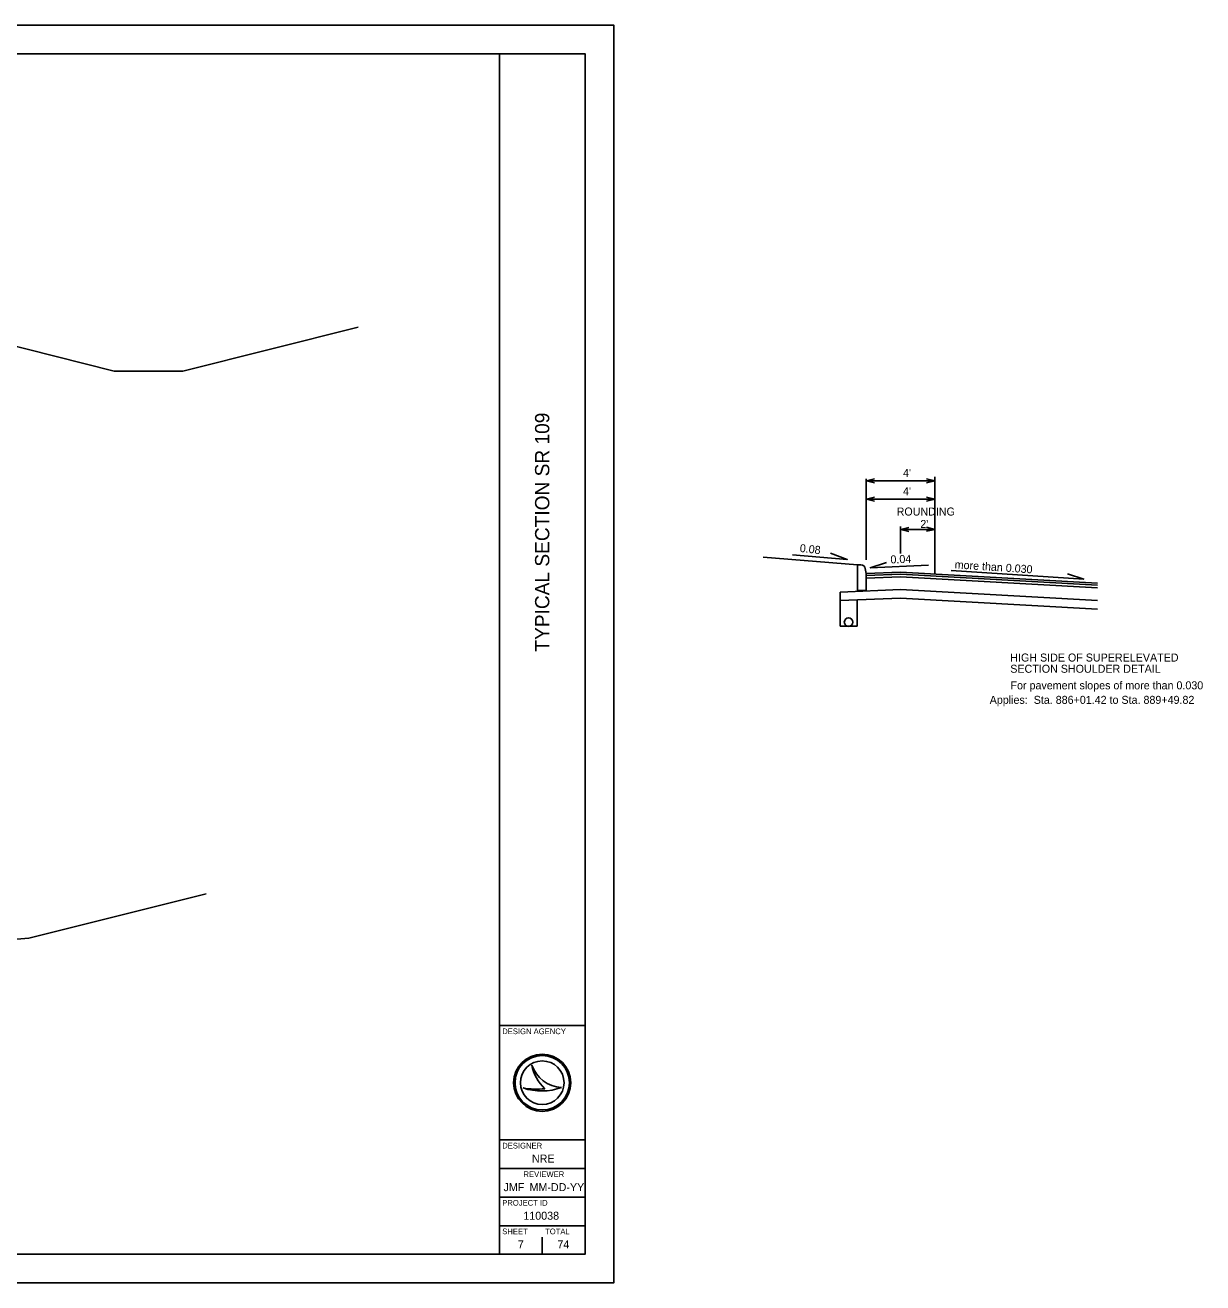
# Model space of a CAD drawing. Extents: x -41 to 222, y -17 to 110.
# Drawn here: x 118.5 to 221.5, y 0 to 110 of the extents above; entities that cross this region are included whole.
import ezdxf

# ---------------------------------------------------------------- set-up
doc = ezdxf.new("R2010")
doc.units = 0
for name, color, linetype in [('Default', 7, 'Continuous'), ('SH_Border', 7, 'Continuous'), ('SH_Cut_Line', 7, 'Continuous'), ('SH_Data', 7, 'Continuous'), ('XS_X_Ground_Line', 7, 'Continuous')]:
    doc.layers.add(name, color=color, linetype=linetype)

msp = doc.modelspace()

# ---------------------------------------------------------------- linework, layer by layer
at = {"layer": 'Default'}
for p, q in [((198.08, 62.89), (198.08, 70.49)), ((192.08, 63.23), (192.08, 70.32)), ((192.11, 70.14), (198.08, 70.14)), ((192.11, 68.53), (198.08, 68.53)), ((198.08, 62.04), (198.08, 68.36)), ((195.08, 63.79), (195.08, 66.14)), ((195.08, 65.89), (198.08, 65.89)), ((191.33, 62.79), (183.08, 63.48)), ((191.33, 60.54), (191.33, 62.79)), ((191.33, 62.79), (191.63, 62.79)), ((192, 62.48), (192.08, 62.04)), ((195.08, 62.17), (192.08, 62.04)), ((192.08, 62.04), (192.08, 60.54)), ((195.08, 61.98), (192.08, 61.86)), ((195.08, 61.76), (192.09, 61.64)), ((195.08, 62.17), (212.33, 61.2)), ((195.08, 61.98), (212.33, 61.02)), ((195.08, 61.76), (212.33, 60.8)), ((195.08, 60.64), (189.8, 60.42)), ((192.08, 60.54), (191.33, 60.54)), ((195.08, 60.64), (212.33, 59.67)), ((189.8, 60.42), (189.8, 59.67)), ((195.08, 59.89), (189.8, 59.67)), ((189.8, 59.67), (189.8, 57.42)), ((191.3, 59.73), (191.3, 57.42)), ((195.08, 59.89), (212.33, 58.92)), ((189.8, 57.42), (191.3, 57.42))]:
    msp.add_line(p, q, dxfattribs=at)
for points in [[(192.81, 69.96), (192.11, 70.14), (192.81, 70.31)], [(197.37, 70.31), (198.08, 70.14), (197.37, 69.96)], [(192.81, 68.36), (192.11, 68.53), (192.81, 68.71)], [(197.37, 68.71), (198.08, 68.53), (197.37, 68.36)], [(195.81, 65.72), (195.11, 65.89), (195.81, 66.07)], [(197.37, 66.08), (198.08, 65.9), (197.37, 65.73)], [(185.64, 63.68), (190.43, 63.27), (188.97, 63.83)], [(197.55, 62.78), (192.44, 62.55), (193.87, 62.99)], [(199.51, 62.31), (211.11, 61.55), (209.7, 62.02)]]:
    msp.add_lwpolyline(points, dxfattribs=at)
msp.add_circle((190.55, 57.79), 0.375, dxfattribs=at)
msp.add_arc((191.63, 62.42), 0.375, 9.4623, 90, dxfattribs=at)
at = {"layer": 'SH_Border'}
for p, q in [((160, 2.5), (160, 107.5)), ((160, 22.5), (167.5, 22.5)), ((160, 12.5), (167.5, 12.5)), ((160, 10), (167.5, 10)), ((160, 7.5), (167.5, 7.5)), ((160, 5), (167.5, 5))]:
    msp.add_line(p, q, dxfattribs=at)
msp.add_lwpolyline([(7.5, 107.5), (167.5, 107.5), (167.5, 2.5), (7.5, 2.5)], close=True, dxfattribs=at)
at = {"layer": 'SH_Cut_Line'}
msp.add_lwpolyline([(0, 0), (170, 0), (170, 110), (0, 110)], close=True, dxfattribs=at)
at = {"layer": 'SH_Data'}
for p, q in [((162.84, 19.05), (162.84, 19.05)), ((162.09, 17.05), (162.09, 17.05)), ((163.75, 17.5), (163.75, 17.5)), ((165.44, 17.09), (165.44, 17.09)), ((161.87, 3.38), (161.87, 3.38)), ((163.75, 2.5), (163.75, 4))]:
    msp.add_line(p, q, dxfattribs=at)
for radius in [2.5, 2.38, 2.38, 1.91]:
    msp.add_circle((163.75, 17.5), radius, dxfattribs=at)
for centre, radius, start, end in [((165.58, 19.99), 2.9, 198.9257, 198.9319), ((166.73, 19.85), 3.98, 191.6379, 191.6421), ((165.58, 19.99), 2.9, 198.9319, 267.1657), ((166.73, 19.85), 3.98, 191.6421, 226.0947), ((163.7, 21.85), 5.07, 251.4576, 290.0832), ((163.24, 23.27), 6.33, 259.4964, 259.4995), ((163.7, 21.85), 5.07, 251.4527, 251.4576), ((163.24, 23.27), 6.33, 259.4995, 276.6672)]:
    msp.add_arc(centre, radius, start, end, dxfattribs=at)
at = {"layer": 'XS_X_Ground_Line'}
for p, q in [((109.93, 83.85), (126.32, 79.75)), ((132.32, 79.75), (147.64, 83.58)), ((132.32, 79.75), (126.32, 79.75)), ((118.84, 30.14), (134.35, 34.02)), ((118.84, 30.14), (110.59, 29.45))]:
    msp.add_line(p, q, dxfattribs=at)

# ---------------------------------------------------------------- texts
at = {"layer": 'Default'}
for s, p in [("4'", (195.31, 70.49)), ("4'", (195.31, 68.89)), ('ROUNDING', (194.75, 67.11)), ("2'", (196.82, 66.02)), ('HIGH SIDE OF SUPERELEVATED', (204.69, 54.34)), ('SECTION SHOULDER DETAIL', (204.69, 53.36)), ('For pavement slopes of more than 0.030', (204.71, 51.91)), ('Applies:  Sta. 886+01.42 to Sta. 889+49.82   ', (202.89, 50.64))]:
    msp.add_text(s, height=0.7, dxfattribs=at).set_placement(p)
for s, rotation, p in [('0.08', 353.6721, (186.25, 63.93)), ('0.04', 1.8627, (194.22, 62.92)), ('more than 0.030', 356.2764, (199.81, 62.49))]:
    msp.add_text(s, height=0.7, rotation=rotation, dxfattribs=at).set_placement(p)
at = {"layer": 'SH_Data'}
msp.add_text('TYPICAL SECTION SR 109', height=1.25, rotation=90, dxfattribs=at).set_placement((164.37, 55.21))
for s, height, p in [('DESIGN AGENCY', 0.5, (160.25, 21.75)), ('DESIGNER', 0.5, (160.25, 11.75)), ('NRE', 0.7, (162.85, 10.52)), ('REVIEWER', 0.5, (162.11, 9.25)), ('JMF', 0.7, (160.37, 8.02)), ('MM-DD-YY', 0.7, (162.64, 8.02)), ('PROJECT ID', 0.5, (160.25, 6.75)), ('110038', 0.7, (162.1, 5.52)), ('SHEET', 0.5, (160.25, 4.25)), ('TOTAL', 0.5, (164, 4.25)), ('7', 0.7, (161.62, 3.02)), ('74', 0.7, (165.08, 3.02))]:
    msp.add_text(s, height=height, dxfattribs=at).set_placement(p)

doc.saveas('drawing.dxf')
